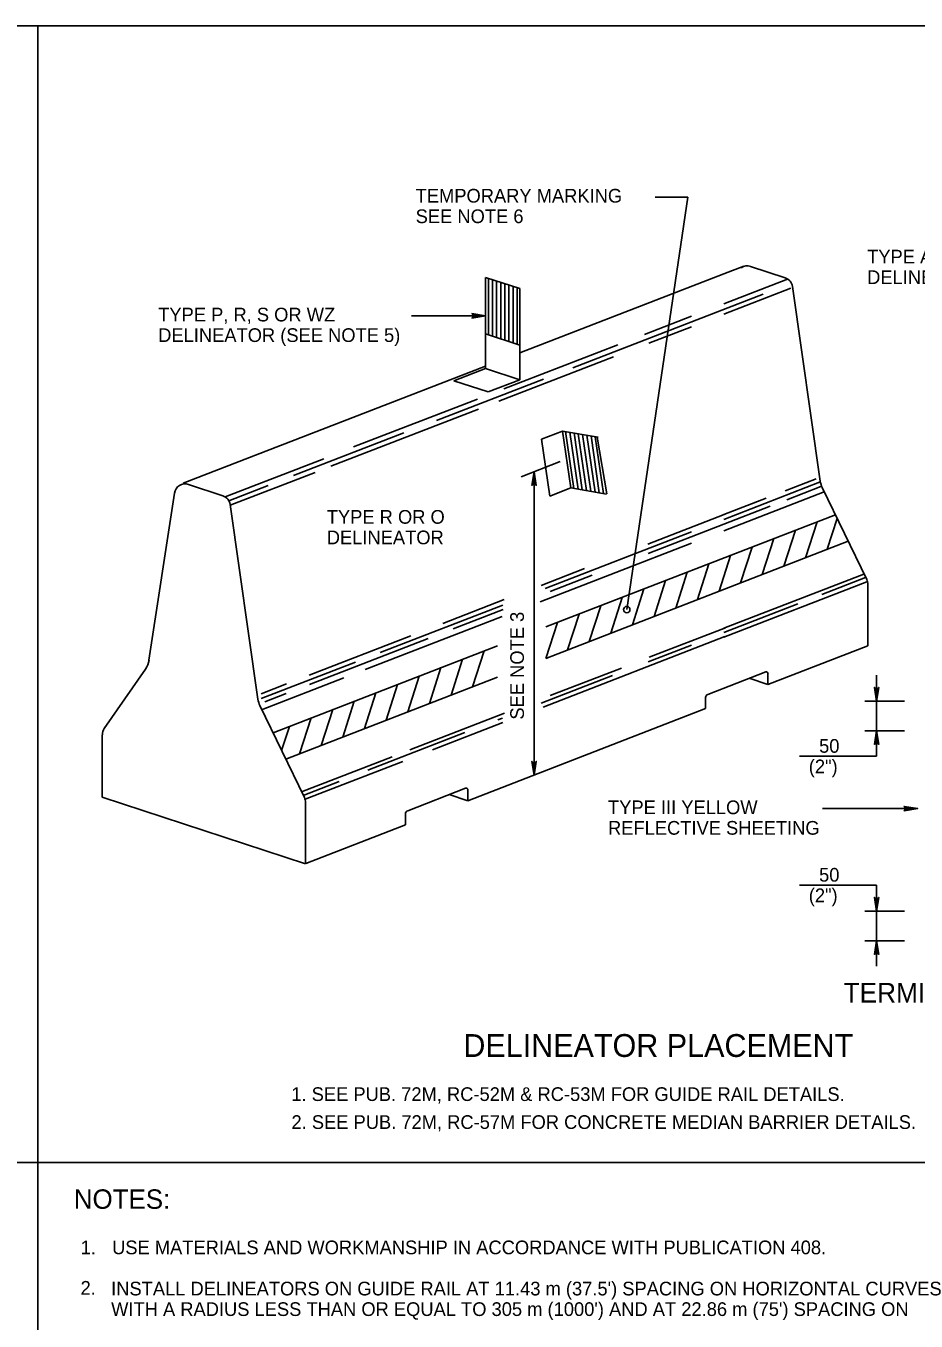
# Model space of a CAD drawing. Extents: x 640253 to 641999, y 298458 to 299646.
# Drawn here: x 640798.8 to 640993.9, y 298753 to 299036.6 of the extents above; entities that cross this region are included whole.
import ezdxf

# ---------------------------------------------------------------- set-up
doc = ezdxf.new("R2010")
doc.units = 0
doc.layers.add('1', color=7, linetype='Continuous')
doc.layers.add('2', color=7, linetype='Continuous')

msp = doc.modelspace()

# ---------------------------------------------------------------- linework, layer by layer
at = {"layer": '1'}
for p, q in [((640293.31, 299036.63), (641079.31, 299036.63)), ((640801.38, 298472.63), (640801.38, 299036.63)), ((640293.31, 298787.67), (641079.31, 298787.67))]:
    msp.add_line(p, q, dxfattribs=at)
at = {"layer": '2'}
for p, q in [((640930.48, 298908.79), (640943.83, 298999.15)), ((640936.73, 298999.15), (640943.83, 298999.15)), ((640951.73, 298982.3), (640956.11, 298984)), ((640957.62, 298983.95), (640965.2, 298981.46)), ((640899.54, 298961.59), (640899.54, 298981.54)), ((640899.54, 298981.54), (640907.03, 298979.08)), ((640900.15, 298968.95), (640900.15, 298981.34)), ((640901.05, 298968.66), (640901.05, 298981.04)), ((640901.95, 298968.36), (640901.95, 298980.75)), ((640907.03, 298965), (640951.73, 298982.3)), ((640951.73, 298975.77), (640965.71, 298981.18)), ((640902.85, 298968.07), (640902.85, 298980.45)), ((640903.75, 298967.77), (640903.75, 298980.16)), ((640904.65, 298967.47), (640904.65, 298979.86)), ((640905.55, 298967.18), (640905.55, 298979.57)), ((640906.45, 298966.89), (640906.45, 298979.27)), ((640907.03, 298959.13), (640907.03, 298979.08)), ((640918.67, 298961.77), (640960.33, 298977.89)), ((640951.73, 298973.49), (640966.43, 298979.19)), ((640966.81, 298979.57), (640972.89, 298936.9)), ((640883.31, 298973.12), (640899.54, 298973.12)), ((640934.34, 298969.05), (640944.63, 298973.03)), ((640899.54, 298969.15), (640907.03, 298966.7)), ((640935.32, 298967.14), (640944.63, 298970.75)), ((640903.5, 298957.11), (640928.55, 298966.8)), ((640902.44, 298954.42), (640927.55, 298964.14)), ((640833.28, 298936.45), (640899.54, 298962.1)), ((640892.6, 298958.9), (640899.54, 298961.59)), ((640899.54, 298961.59), (640907.03, 298959.13)), ((640888.78, 298950.2), (640912.25, 298959.29)), ((640892.6, 298958.9), (640900.09, 298956.45)), ((640900.09, 298956.45), (640907.03, 298959.13)), ((640865.65, 298940.18), (640897.97, 298952.69)), ((640870.62, 298944.4), (640897.74, 298954.86)), ((640857.44, 298938.14), (640881.63, 298947.51)), ((640911.77, 298946.1), (640916.42, 298947.9)), ((640918.23, 298935.45), (640916.42, 298947.9)), ((640916.42, 298947.9), (640924.18, 298946.55)), ((640918.86, 298935.34), (640917.05, 298947.8)), ((640919.79, 298935.18), (640917.98, 298947.63)), ((640920.73, 298935.01), (640918.92, 298947.47)), ((640921.66, 298934.85), (640919.85, 298947.31)), ((640922.59, 298934.69), (640920.78, 298947.14)), ((640923.53, 298934.53), (640921.72, 298946.98)), ((640924.46, 298934.36), (640922.65, 298946.82)), ((640925.39, 298934.2), (640923.58, 298946.65)), ((640926.07, 298934.14), (640924, 298946.55)), ((640913.58, 298933.64), (640911.77, 298946.1)), ((640842.48, 298933.48), (640864.06, 298941.84)), ((640907.33, 298937.88), (640915.87, 298941.19)), ((640843.59, 298931.63), (640862.22, 298938.84)), ((640910.16, 298872.55), (640910.16, 298938.98)), ((640834.4, 298936.2), (640841.97, 298933.71)), ((640843.3, 298932.64), (640851.92, 298935.99)), ((640913.58, 298933.64), (640918.23, 298935.45)), ((640918.23, 298935.45), (640926, 298934.1)), ((640951.73, 298928.54), (640972.74, 298936.66)), ((640965.17, 298934.8), (640972.01, 298937.43)), ((640965.56, 298932.85), (640972.98, 298935.73)), ((640973.31, 298935.51), (640983.05, 298915.35)), ((640831.35, 298934.32), (640825.77, 298897.72)), ((640951.73, 298926.06), (640973.75, 298934.58)), ((640951.73, 298929.6), (640961.03, 298933.2)), ((640843.56, 298931.81), (640849.66, 298889.14)), ((640912.75, 298904.98), (640976.19, 298929.55)), ((640935.08, 298923.15), (640951.84, 298929.63)), ((640951.73, 298927.5), (640961.88, 298931.43)), ((640935.13, 298921.08), (640951.73, 298927.51)), ((640972.18, 298928), (640969.66, 298920.15)), ((640976.57, 298928.75), (640974.4, 298921.99)), ((640912.6, 298913.39), (640944.63, 298925.78)), ((640912.75, 298898.11), (640978.99, 298923.76)), ((640962.69, 298924.32), (640960.17, 298916.48)), ((640967.44, 298926.16), (640964.91, 298918.31)), ((640911.52, 298910.51), (640944.63, 298923.33)), ((640957.95, 298922.49), (640955.43, 298914.64)), ((640948.47, 298918.81), (640945.95, 298910.97)), ((640953.21, 298920.65), (640950.69, 298912.8)), ((640911.68, 298914.09), (640921.19, 298917.78)), ((640913.67, 298912.78), (640922.86, 298916.32)), ((640943.73, 298916.98), (640941.2, 298909.13)), ((640951.73, 298904.7), (640982.45, 298916.56)), ((640973.21, 298912.07), (640982.82, 298915.81)), ((640934.24, 298913.3), (640931.72, 298905.46)), ((640938.98, 298915.14), (640936.46, 298907.29)), ((640951.73, 298902.74), (640983.05, 298914.87)), ((640983.29, 298914.32), (640983.29, 298900.86)), ((640876.42, 298899.37), (640903.32, 298909.79)), ((640890.15, 298905.75), (640903.6, 298910.96)), ((640924.76, 298909.63), (640922.23, 298901.78)), ((640929.5, 298911.47), (640926.98, 298903.62)), ((640951.73, 298903.77), (640967.93, 298910.04)), ((640873.14, 298895.63), (640903.14, 298907.25)), ((640892.41, 298904.56), (640903.4, 298908.81)), ((640920.01, 298907.79), (640917.49, 298899.95)), ((640915.27, 298905.96), (640912.75, 298898.11)), ((640935.37, 298898.34), (640952.1, 298904.81)), ((640860.9, 298894.44), (640883.13, 298903.03)), ((640860.95, 298892.35), (640886.96, 298902.42)), ((640912.16, 298887.44), (640951.99, 298902.87)), ((640852.95, 298881.82), (640902.12, 298900.87)), ((640899.22, 298899.74), (640896.7, 298891.89)), ((640935.16, 298897.37), (640944.63, 298901.03)), ((640961.42, 298892.38), (640983.29, 298900.86)), ((640825.01, 298895.75), (640815.96, 298882.72)), ((640850.38, 298889.29), (640871.03, 298897.3)), ((640889.74, 298896.07), (640887.22, 298888.22)), ((640894.48, 298897.9), (640891.96, 298890.06)), ((640913.72, 298889.96), (640929.3, 298895.99)), ((640850.45, 298886.85), (640868.5, 298893.85)), ((640855.75, 298876.03), (640902.12, 298893.99)), ((640885, 298894.23), (640882.47, 298886.38)), ((640911.7, 298888.29), (640927.37, 298894.35)), ((640961.42, 298892.38), (640957.3, 298893.74)), ((640985.22, 298894.44), (640985.22, 298876.68)), ((640850.34, 298890.33), (640855.91, 298892.49)), ((640851.13, 298888.56), (640855.81, 298890.38)), ((640875.51, 298890.56), (640872.99, 298882.71)), ((640880.25, 298892.39), (640877.73, 298884.55)), ((640961.42, 298892.39), (640961.42, 298892.39)), ((640850.08, 298887.75), (640859.83, 298867.6)), ((640866.03, 298886.88), (640863.51, 298879.04)), ((640870.77, 298888.72), (640868.25, 298880.87)), ((640895.65, 298866.93), (640947.76, 298887.1)), ((640982.63, 298888.75), (640991.3, 298888.75)), ((640861.29, 298885.05), (640858.76, 298877.2)), ((640882.95, 298878.05), (640903.7, 298886.08)), ((640882.95, 298878.05), (640903.35, 298885.95)), ((640902.25, 298884.65), (640903.23, 298885.02)), ((640815.54, 298867.73), (640815.54, 298881.38)), ((640856.54, 298883.21), (640854.84, 298877.91)), ((640873.7, 298873.59), (640894.99, 298881.83)), ((640887.9, 298878.04), (640903.35, 298884.03)), ((640982.63, 298882.25), (640991.3, 298882.25)), ((640859.22, 298868.86), (640879.09, 298876.55)), ((640985.22, 298876.68), (640968.31, 298876.68)), ((640860, 298867.24), (640881.4, 298875.52)), ((640859.58, 298868.1), (640867.42, 298871.15)), ((640860.06, 298853.07), (640815.54, 298867.73)), ((640895.65, 298866.93), (640891.57, 298868.26)), ((640860.06, 298866.57), (640860.06, 298853.07)), ((640973.4, 298865.2), (640994.25, 298865.2)), ((640860.12, 298853.17), (640881.99, 298861.64)), ((640881.99, 298861.64), (640881.99, 298861.64)), ((640985.22, 298848.44), (640968.31, 298848.44)), ((640985.22, 298848.44), (640985.22, 298830.68)), ((640982.63, 298842.75), (640991.3, 298842.75)), ((640982.63, 298836.25), (640991.3, 298836.25))]:
    msp.add_line(p, q, dxfattribs=at)
for points in [[(640896.69, 298973.48), (640896.79, 298973.28), (640899.54, 298973.12), (640896.69, 298973.48), (640896.54, 298973.61), (640899.54, 298973.12), (640896.8, 298972.99), (640896.7, 298972.79), (640899.54, 298973.12), (640896.54, 298972.65), (640896.7, 298972.79)], [(640909.8, 298936.12), (640910.01, 298936.23), (640910.16, 298938.98), (640909.8, 298936.12), (640909.68, 298935.98), (640910.16, 298938.98), (640910.3, 298936.23), (640910.5, 298936.13), (640910.16, 298938.98), (640910.64, 298935.98), (640910.5, 298936.13)], [(640948.23, 298890.19), (640960.93, 298895.13)], [(640961.42, 298894.78), (640961.42, 298892.38)], [(640985.58, 298891.6), (640985.37, 298891.49), (640985.22, 298888.75), (640985.58, 298891.6), (640985.7, 298891.75), (640985.22, 298888.75), (640985.08, 298891.49), (640984.88, 298891.59), (640985.22, 298888.75), (640984.74, 298891.75), (640984.88, 298891.59)], [(640947.76, 298887.11), (640947.76, 298889.51)], [(640984.86, 298879.39), (640985.06, 298879.5), (640985.22, 298882.25), (640984.86, 298879.39), (640984.73, 298879.25), (640985.22, 298882.25), (640985.35, 298879.5), (640985.56, 298879.4), (640985.22, 298882.25), (640985.69, 298879.25), (640985.56, 298879.4)], [(640910.52, 298875.4), (640910.31, 298875.3), (640910.16, 298872.55), (640910.52, 298875.4), (640910.64, 298875.55), (640910.16, 298872.55), (640910.03, 298875.29), (640909.82, 298875.39), (640910.16, 298872.55), (640909.68, 298875.55), (640909.82, 298875.39)], [(640882.46, 298864.73), (640895.16, 298869.66)], [(640895.65, 298869.32), (640895.65, 298866.93)], [(640991.4, 298865.56), (640991.5, 298865.35), (640994.25, 298865.2), (640991.4, 298865.56), (640991.25, 298865.69), (640994.25, 298865.2), (640991.51, 298865.07), (640991.41, 298864.86), (640994.25, 298865.2), (640991.25, 298864.73), (640991.41, 298864.86)], [(640881.99, 298861.64), (640881.99, 298864.04)], [(640985.58, 298845.6), (640985.37, 298845.49), (640985.22, 298842.75), (640985.58, 298845.6), (640985.7, 298845.75), (640985.22, 298842.75), (640985.08, 298845.49), (640984.88, 298845.59), (640985.22, 298842.75), (640984.74, 298845.75), (640984.88, 298845.59)], [(640984.86, 298833.39), (640985.06, 298833.5), (640985.22, 298836.25), (640984.86, 298833.39), (640984.73, 298833.25), (640985.22, 298836.25), (640985.35, 298833.5), (640985.56, 298833.4), (640985.22, 298836.25), (640985.69, 298833.25), (640985.56, 298833.4)]]:
    msp.add_lwpolyline(points, dxfattribs=at)
msp.add_circle((640930.48, 298908.79), 0.691, dxfattribs=at)
for centre, radius, start, end in [((640956.9, 298981.73), 2.34, 71.7735, 124.6618), ((640964.47, 298979.23), 2.34, 8.1301, 71.7736), ((640833.67, 298933.97), 2.34, 71.7735, 171.3546), ((640977.53, 298937.56), 4.69, 188.13, 205.8211), ((640841.24, 298931.48), 2.34, 8.1301, 71.7736), ((640980.95, 298914.34), 2.34, 0, 25.821), ((640821.15, 298898.43), 4.69, 325.2567, 351.3547), ((640961.06, 298894.79), 0.366, 0, 111.2452), ((640948.49, 298889.51), 0.732, 111.1757, 180), ((640854.3, 298889.81), 4.69, 188.13, 205.8211), ((640817.89, 298881.39), 2.34, 145.2568, 180), ((640857.72, 298866.59), 2.34, 0, 25.821), ((640895.29, 298869.32), 0.366, 0, 111.2554), ((640882.72, 298864.06), 0.732, 111.1757, 180)]:
    msp.add_arc(centre, radius, start, end, dxfattribs=at)

# ---------------------------------------------------------------- texts
for s, height, p in [('TEMPORARY MARKING', 3, (640884.21, 298997.93)), ('SEE NOTE 6', 3, (640884.21, 298993.43)), ('TYPE A or B', 3, (640983.15, 298984.59)), ('DELINEATOR', 3, (640983.15, 298980.09)), ('TYPE P, R, S OR WZ ', 3, (640827.79, 298971.9)), ('DELINEATOR (SEE NOTE 5)', 3, (640827.79, 298967.4)), ('TYPE R OR O', 3, (640864.73, 298927.59)), ('DELINEATOR', 3, (640864.73, 298923.09)), ('50', 3, (640972.62, 298877.43)), ('(2")', 3, (640970.36, 298872.93)), ('TYPE III YELLOW', 3, (640926.37, 298863.98)), ('REFLECTIVE SHEETING', 3, (640926.37, 298859.48)), ('50', 3, (640972.62, 298849.2)), ('(2")', 3, (640970.36, 298844.7)), ('TERMINAL SECTION DETAIL', 4.3, (640977.99, 298822.71)), ('DELINEATOR PLACEMENT', 5, (640894.66, 298810.81)), ('1. SEE PUB. 72M, RC-52M & RC-53M FOR GUIDE RAIL DETAILS.', 3, (640856.96, 298801.16)), ('2. SEE PUB. 72M, RC-57M FOR CONCRETE MEDIAN BARRIER DETAILS.', 3, (640857, 298795.04)), ('NOTES:', 4.25, (640809.29, 298777.55)), ('1.', 3, (640810.79, 298767.58)), ('USE MATERIALS AND WORKMANSHIP IN ACCORDANCE WITH PUBLICATION 408.', 3, (640817.69, 298767.59)), ('2.', 3, (640810.78, 298758.73)), ("INSTALL DELINEATORS ON GUIDE RAIL AT 11.43 m (37.5') SPACING ON HORIZONTAL CURVES", 3, (640817.48, 298758.57)), ("WITH A RADIUS LESS THAN OR EQUAL TO 305 m (1000') AND AT 22.86 m (75') SPACING ON", 3, (640817.48, 298754.07))]:
    msp.add_text(s, height=height, dxfattribs=at).set_placement(p)
msp.add_text('SEE NOTE 3', height=3, rotation=90, dxfattribs=at).set_placement((640907.94, 298884.68))

doc.saveas('drawing.dxf')
